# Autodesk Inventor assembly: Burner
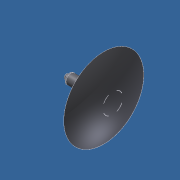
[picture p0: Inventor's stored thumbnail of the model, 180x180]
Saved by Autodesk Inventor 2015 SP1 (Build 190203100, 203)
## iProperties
Category: Mechanical Engineering Drawing and Design - CADD
Manager: Fábio Ricardo de Oliveira Souza
Company: SENAI - Serviço Nacional de Aprendizagem Industrial
Created: 2011-06
Part Number: Burner
Document SubType Name: Weldment
Designer: Guilherme Augusto Franco de Souza
Engineer: George Geraldo de Oliveia Silva
Authority: Fábio Ricardo de Oliveira Soza
Weld Material: Welded Stainless Steel, 440C
Description: Sub-assembly
Mass: 13687.5 g
Surface Area: 34965.1 cm^2
Volume: 1743.66 cm^3
Density: 7.84989 g/cm^3
Subject: WorldSkill 2011 - London, England
Author: Guilherme Augusto Franco de Souza
Revision Number: 00
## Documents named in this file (8)
- E:\Visitor Experience Project\WSI2015 - Visitor Experience Project\#46- Sheet Metal Technology\01- 3D Models\Outodoor Heater\2- Assemblies\Burner.iam
- E:\Visitor Experience Project\WSI2015 - Visitor Experience Project\#46- Sheet Metal Technology\01- 3D Models\Outodoor Heater\1- Parts\Hat.ipt
- E:\Visitor Experience Project\WSI2015 - Visitor Experience Project\#46- Sheet Metal Technology\01- 3D Models\Outodoor Heater\1- Parts\Cone\Cone-01.ipt
- C:\Users\SENAI\Desktop\WorldSkill 2011\Workspace\2011-06-14\1- Parts\Cone.ipt
- E:\Visitor Experience Project\WSI2015 - Visitor Experience Project\#46- Sheet Metal Technology\01- 3D Models\Outodoor Heater\1- Parts\Cone\Cone-02.ipt
- E:\Visitor Experience Project\WSI2015 - Visitor Experience Project\#46- Sheet Metal Technology\01- 3D Models\Outodoor Heater\1- Parts\Tube\Tube-02.ipt
- C:\Users\SENAI\Desktop\WorldSkill 2011\Workspace\2011-06-14\1- Parts\Tube.ipt
- E:\Visitor Experience Project\WSI2015 - Visitor Experience Project\#46- Sheet Metal Technology\01- 3D Models\Outodoor Heater\1- Parts\Tube\Tube-01.ipt
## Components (5 placed, 5 different names)
1. Hat:1 — Mate:1, Flush:1, Flush:2
2. Cone-01:1 — Insert:1
3. Cone-02:2 — Insert:2, Insert:3
4. Tube-02:1 — Insert:1, Insert:2
5. Tube-01:2 — Insert:3, Mate:1, Flush:1, Flush:2
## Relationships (6: Insert 3, Flush 2, Mate 1)
- Insert:1: Cone-01:1 ↔ Tube-02:1
- Insert:2: Cone-02:2 ↔ Tube-02:1
- Insert:3: Cone-02:2 ↔ Tube-01:2
- Mate:1: Hat:1 ↔ Tube-01:2
- Flush:1: Hat:1 ↔ Tube-01:2
- Flush:2: Hat:1 ↔ Tube-01:2
